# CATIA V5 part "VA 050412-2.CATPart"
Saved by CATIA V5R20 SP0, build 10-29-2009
Part number: VA 050412-2
Revision: ANY
Definition: UNKNOWN
Nomenclature: VA 050412-2
Source: Unknown
Bounding box of the stored display mesh (mm): x -2.5 to 2.5, y 0 to 11.996, z -2.5 to 2.5
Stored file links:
  C:\Users\Utente\Desktop\IO LAVORO\3D X SITO CF\CUMSA\3D files VA\VA 050412\VA 050412-2.CATPart
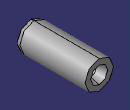
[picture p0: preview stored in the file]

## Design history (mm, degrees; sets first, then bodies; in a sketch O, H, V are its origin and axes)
Body1 "Revolución1" (main body)
  Solid1: solid without history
